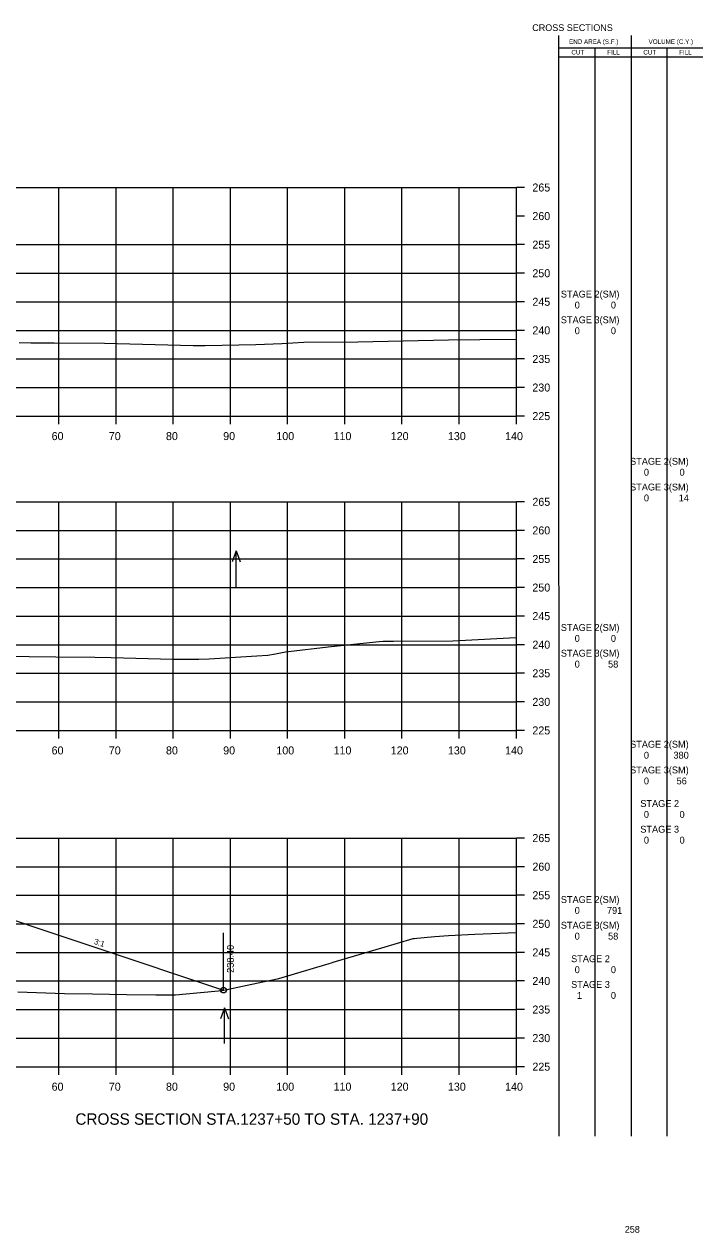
# Model space of a CAD drawing. Extents: x 1342547 to 1344156, y -1532351 to -1517216.
# Drawn here: x 1342756.8 to 1342875.5, y -1529164 to -1528952.5 of the extents above; entities that cross this region are included whole.
import ezdxf

# ---------------------------------------------------------------- set-up
doc = ezdxf.new("R2010")
doc.units = 0
for name, color, linetype in [('Level 2', 7, 'Continuous'), ('R_Axis', 7, 'Continuous'), ('R_Axis Annot', 7, 'Continuous'), ('R_Border Notes', 7, 'Continuous'), ('R_Draft', 7, 'Continuous'), ('R_Exist Surface', 7, 'Continuous'), ('R_Fin Surface', 7, 'Continuous'), ('R_Grid', 7, 'Continuous'), ('R_No Plot', 7, 'Continuous'), ('R_Water', 7, 'Continuous'), ('R_Xsect Elev', 7, 'Continuous'), ('R_Xsect Slope', 7, 'Continuous')]:
    doc.layers.add(name, color=color, linetype=linetype)

msp = doc.modelspace()

# ---------------------------------------------------------------- linework, layer by layer
at = {"layer": 'Level 2'}
for p, q in [((1342850.33, -1529147.08), (1342850.32, -1528954.48)), ((1342862.99, -1529147.08), (1342862.99, -1528954.48)), ((1342850.32, -1528956.64), (1342863.59, -1528956.64)), ((1342856.66, -1529147.08), (1342856.66, -1528956.64)), ((1342863.59, -1528956.64), (1342875.48, -1528956.64)), ((1342869.23, -1529147.08), (1342869.23, -1528956.64)), ((1342850.32, -1528958.2), (1342863.59, -1528958.2)), ((1342863.59, -1528958.2), (1342875.48, -1528958.2))]:
    msp.add_line(p, q, dxfattribs=at)
at = {"layer": 'R_Axis'}
for p, q in [((1342842.87, -1529021.08), (1342842.87, -1528981.08)), ((1342844.27, -1528981.08), (1342842.87, -1528981.08)), ((1342844.27, -1528986.08), (1342842.87, -1528986.08)), ((1342844.27, -1528991.08), (1342842.87, -1528991.08)), ((1342844.27, -1528996.08), (1342842.87, -1528996.08)), ((1342844.27, -1529001.08), (1342842.87, -1529001.08)), ((1342844.27, -1529006.08), (1342842.87, -1529006.08)), ((1342844.27, -1529011.08), (1342842.87, -1529011.08)), ((1342844.27, -1529016.08), (1342842.87, -1529016.08)), ((1342562.87, -1529021.08), (1342842.87, -1529021.08)), ((1342762.87, -1529022.48), (1342762.87, -1529021.08)), ((1342772.87, -1529022.48), (1342772.87, -1529021.08)), ((1342782.87, -1529022.48), (1342782.87, -1529021.08)), ((1342792.87, -1529022.48), (1342792.87, -1529021.08)), ((1342802.87, -1529022.48), (1342802.87, -1529021.08)), ((1342812.87, -1529022.48), (1342812.87, -1529021.08)), ((1342822.87, -1529022.48), (1342822.87, -1529021.08)), ((1342832.87, -1529022.48), (1342832.87, -1529021.08)), ((1342842.87, -1529022.48), (1342842.87, -1529021.08)), ((1342844.27, -1529021.08), (1342842.87, -1529021.08)), ((1342842.87, -1529076.08), (1342842.87, -1529036.08)), ((1342844.27, -1529036.08), (1342842.87, -1529036.08)), ((1342844.27, -1529041.08), (1342842.87, -1529041.08)), ((1342844.27, -1529046.08), (1342842.87, -1529046.08)), ((1342844.27, -1529051.08), (1342842.87, -1529051.08)), ((1342844.27, -1529056.08), (1342842.87, -1529056.08)), ((1342844.27, -1529061.08), (1342842.87, -1529061.08)), ((1342844.27, -1529066.08), (1342842.87, -1529066.08)), ((1342844.27, -1529071.08), (1342842.87, -1529071.08)), ((1342562.87, -1529076.08), (1342842.87, -1529076.08)), ((1342762.87, -1529077.48), (1342762.87, -1529076.08)), ((1342772.87, -1529077.48), (1342772.87, -1529076.08)), ((1342782.87, -1529077.48), (1342782.87, -1529076.08)), ((1342792.87, -1529077.48), (1342792.87, -1529076.08)), ((1342802.87, -1529077.48), (1342802.87, -1529076.08)), ((1342812.87, -1529077.48), (1342812.87, -1529076.08)), ((1342822.87, -1529077.48), (1342822.87, -1529076.08)), ((1342832.87, -1529077.48), (1342832.87, -1529076.08)), ((1342842.87, -1529077.48), (1342842.87, -1529076.08)), ((1342844.27, -1529076.08), (1342842.87, -1529076.08)), ((1342842.87, -1529134.92), (1342842.87, -1529094.92)), ((1342844.27, -1529094.92), (1342842.87, -1529094.92)), ((1342844.27, -1529099.92), (1342842.87, -1529099.92)), ((1342844.27, -1529104.92), (1342842.87, -1529104.92)), ((1342844.27, -1529109.92), (1342842.87, -1529109.92)), ((1342844.27, -1529114.92), (1342842.87, -1529114.92)), ((1342844.27, -1529119.92), (1342842.87, -1529119.92)), ((1342844.27, -1529124.92), (1342842.87, -1529124.92)), ((1342844.27, -1529129.92), (1342842.87, -1529129.92)), ((1342562.87, -1529134.92), (1342842.87, -1529134.92)), ((1342762.87, -1529136.32), (1342762.87, -1529134.92)), ((1342772.87, -1529136.32), (1342772.87, -1529134.92)), ((1342782.87, -1529136.32), (1342782.87, -1529134.92)), ((1342792.87, -1529136.32), (1342792.87, -1529134.92)), ((1342802.87, -1529136.32), (1342802.87, -1529134.92)), ((1342812.87, -1529136.32), (1342812.87, -1529134.92)), ((1342822.87, -1529136.32), (1342822.87, -1529134.92)), ((1342832.87, -1529136.32), (1342832.87, -1529134.92)), ((1342842.87, -1529136.32), (1342842.87, -1529134.92)), ((1342844.27, -1529134.92), (1342842.87, -1529134.92))]:
    msp.add_line(p, q, dxfattribs=at)
at = {"layer": 'R_Exist Surface'}
for points in [[(1342755.91, -1529008.21), (1342757.97, -1529008.26), (1342762.04, -1529008.28), (1342770.87, -1529008.29), (1342786.38, -1529008.71), (1342786.97, -1529008.72), (1342788.46, -1529008.7), (1342797.3, -1529008.58), (1342801.84, -1529008.36), (1342805.71, -1529008.15), (1342815.14, -1529008.06), (1342831.01, -1529007.72), (1342836.46, -1529007.68), (1342842.87, -1529007.61)], [(1342754.94, -1529063.11), (1342757.66, -1529063.17), (1342762.35, -1529063.2), (1342769.14, -1529063.28), (1342772, -1529063.34), (1342782.82, -1529063.64), (1342787.32, -1529063.62), (1342789.15, -1529063.58), (1342797.5, -1529063.04), (1342799.41, -1529062.89), (1342800.78, -1529062.65), (1342802.52, -1529062.34), (1342810.51, -1529061.38), (1342818.9, -1529060.51), (1342819.6, -1529060.47), (1342821.41, -1529060.48), (1342831.79, -1529060.42), (1342832.88, -1529060.37), (1342842.77, -1529059.81), (1342842.87, -1529059.8)], [(1342755.69, -1529121.81), (1342763.85, -1529122.13), (1342768.74, -1529122.18), (1342774.7, -1529122.3), (1342779.84, -1529122.34), (1342783.26, -1529122.33), (1342786.99, -1529122.02), (1342791.42, -1529121.56), (1342798.51, -1529120.06), (1342801.32, -1529119.46), (1342810.15, -1529116.85), (1342810.57, -1529116.72), (1342810.86, -1529116.63), (1342811.39, -1529116.43), (1342819.36, -1529114.13), (1342824.84, -1529112.51), (1342824.98, -1529112.48), (1342825.47, -1529112.41), (1342828.61, -1529112.12), (1342831.01, -1529111.98), (1342835.61, -1529111.75), (1342842.87, -1529111.43)]]:
    msp.add_lwpolyline(points, dxfattribs=at)
at = {"layer": 'R_Fin Surface'}
msp.add_lwpolyline([(1342649.15, -1529113.28), (1342653.18, -1529113.2), (1342659.86, -1529110.98), (1342659.87, -1529110.98), (1342671.37, -1529110.35), (1342673.37, -1529110.24), (1342702.87, -1529108.61), (1342732.37, -1529106.99), (1342734.37, -1529106.88), (1342745.87, -1529106.25), (1342745.88, -1529106.25), (1342791.66, -1529121.51)], dxfattribs=at)
at = {"layer": 'R_Grid'}
for p, q in [((1342562.87, -1528981.08), (1342842.87, -1528981.08)), ((1342762.87, -1529021.08), (1342762.87, -1528981.08)), ((1342772.87, -1529021.08), (1342772.87, -1528981.08)), ((1342782.87, -1529021.08), (1342782.87, -1528981.08)), ((1342792.87, -1529021.08), (1342792.87, -1528981.08)), ((1342802.87, -1529021.08), (1342802.87, -1528981.08)), ((1342812.87, -1529021.08), (1342812.87, -1528981.08)), ((1342822.87, -1529021.08), (1342822.87, -1528981.08)), ((1342832.87, -1529021.08), (1342832.87, -1528981.08)), ((1342842.87, -1529021.08), (1342842.87, -1528981.08)), ((1342562.87, -1528991.08), (1342842.87, -1528991.08)), ((1342562.87, -1528996.08), (1342842.87, -1528996.08)), ((1342562.87, -1529001.08), (1342842.87, -1529001.08)), ((1342562.87, -1529006.08), (1342842.87, -1529006.08)), ((1342562.87, -1529011.08), (1342842.87, -1529011.08)), ((1342562.87, -1529016.08), (1342842.87, -1529016.08)), ((1342562.87, -1529021.08), (1342842.87, -1529021.08)), ((1342562.87, -1529036.08), (1342842.87, -1529036.08)), ((1342762.87, -1529076.08), (1342762.87, -1529036.08)), ((1342772.87, -1529076.08), (1342772.87, -1529036.08)), ((1342782.87, -1529076.08), (1342782.87, -1529036.08)), ((1342792.87, -1529076.08), (1342792.87, -1529036.08)), ((1342802.87, -1529076.08), (1342802.87, -1529036.08)), ((1342812.87, -1529076.08), (1342812.87, -1529036.08)), ((1342822.87, -1529076.08), (1342822.87, -1529036.08)), ((1342832.87, -1529076.08), (1342832.87, -1529036.08)), ((1342842.87, -1529076.08), (1342842.87, -1529036.08)), ((1342562.87, -1529041.08), (1342842.87, -1529041.08)), ((1342562.87, -1529046.08), (1342842.87, -1529046.08)), ((1342562.87, -1529051.08), (1342842.87, -1529051.08)), ((1342562.87, -1529056.08), (1342842.87, -1529056.08)), ((1342562.87, -1529061.08), (1342842.87, -1529061.08)), ((1342562.87, -1529066.08), (1342842.87, -1529066.08)), ((1342562.87, -1529071.08), (1342842.87, -1529071.08)), ((1342562.87, -1529076.08), (1342842.87, -1529076.08)), ((1342562.87, -1529094.92), (1342842.87, -1529094.92)), ((1342762.87, -1529134.92), (1342762.87, -1529094.92)), ((1342772.87, -1529134.92), (1342772.87, -1529094.92)), ((1342782.87, -1529134.92), (1342782.87, -1529094.92)), ((1342792.87, -1529134.92), (1342792.87, -1529094.92)), ((1342802.87, -1529134.92), (1342802.87, -1529094.92)), ((1342812.87, -1529134.92), (1342812.87, -1529094.92)), ((1342822.87, -1529134.92), (1342822.87, -1529094.92)), ((1342832.87, -1529134.92), (1342832.87, -1529094.92)), ((1342842.87, -1529134.92), (1342842.87, -1529094.92)), ((1342562.87, -1529099.92), (1342842.87, -1529099.92)), ((1342562.87, -1529104.92), (1342842.87, -1529104.92)), ((1342562.87, -1529109.92), (1342842.87, -1529109.92)), ((1342562.87, -1529114.92), (1342842.87, -1529114.92)), ((1342562.87, -1529119.92), (1342842.87, -1529119.92)), ((1342562.87, -1529124.92), (1342842.87, -1529124.92)), ((1342562.87, -1529129.92), (1342842.87, -1529129.92)), ((1342562.87, -1529134.92), (1342842.87, -1529134.92))]:
    msp.add_line(p, q, dxfattribs=at)
at = {"layer": 'R_No Plot'}
msp.add_circle((1342791.66, -1529121.51), 0.5, dxfattribs=at)
at = {"layer": 'R_Water'}
for p, q in [((1342793.86, -1529044.66), (1342793.16, -1529046.59)), ((1342793.86, -1529050.95), (1342793.86, -1529044.66)), ((1342793.86, -1529044.66), (1342794.56, -1529046.59)), ((1342791.84, -1529124.6), (1342791.14, -1529126.52)), ((1342791.84, -1529130.88), (1342791.84, -1529124.6)), ((1342791.84, -1529124.6), (1342792.54, -1529126.52))]:
    msp.add_line(p, q, dxfattribs=at)
at = {"layer": 'R_Xsect Elev'}
msp.add_line((1342791.66, -1529121.51), (1342791.66, -1529111.51), dxfattribs=at)

# ---------------------------------------------------------------- texts
at = {"layer": 'Level 2'}
for s, height, p in [('END AREA (S.F.)', 0.7937, (1342852.08, -1528955.95)), ('CUT', 0.794, (1342852.5, -1528957.81)), ('FILL', 0.794, (1342858.76, -1528957.81)), ('CUT', 0.794, (1342865.07, -1528957.81)), ('VOLUME (C.Y.)', 0.7937, (1342865.99, -1528955.95)), ('FILL', 0.794, (1342871.33, -1528957.81)), (' STAGE 2(SM)  ', 1.2, (1342850.2, -1529000.33)), ('0', 1.2, (1342853.07, -1529002.25)), ('0', 1.2, (1342859.4, -1529002.25)), (' STAGE 3(SM)  ', 1.2, (1342850.2, -1529004.83)), ('0', 1.2, (1342853.07, -1529006.75)), ('0', 1.2, (1342859.4, -1529006.75)), (' STAGE 2(SM)  ', 1.2, (1342862.31, -1529029.59)), ('0', 1.2, (1342865.17, -1529031.5)), ('0', 1.2, (1342871.41, -1529031.5)), (' STAGE 3(SM)  ', 1.2, (1342862.31, -1529034.09)), ('0', 1.2, (1342865.17, -1529036)), ('14', 1.2, (1342871.27, -1529036)), (' STAGE 2(SM)  ', 1.2, (1342850.2, -1529058.67)), ('0', 1.2, (1342853.07, -1529060.58)), ('0', 1.2, (1342859.4, -1529060.58)), (' STAGE 3(SM)  ', 1.2, (1342850.2, -1529063.17)), ('0', 1.2, (1342853.07, -1529065.08)), ('58', 1.2, (1342858.91, -1529065.08)), (' STAGE 2(SM)  ', 1.2, (1342862.31, -1529079.1)), ('0', 1.2, (1342865.17, -1529081.02)), ('380', 1.2, (1342870.34, -1529081.02)), (' STAGE 3(SM)  ', 1.2, (1342862.31, -1529083.6)), ('0', 1.2, (1342865.17, -1529085.52)), ('56', 1.2, (1342870.89, -1529085.52)), (' STAGE 2 ', 1.2, (1342864.1, -1529089.47)), ('0', 1.2, (1342865.17, -1529091.38)), ('0', 1.2, (1342871.41, -1529091.38)), (' STAGE 3 ', 1.2, (1342864.1, -1529093.97)), ('0', 1.2, (1342865.17, -1529095.88)), ('0', 1.2, (1342871.41, -1529095.88)), (' STAGE 2(SM)  ', 1.2, (1342850.2, -1529106.27)), ('0', 1.2, (1342853.07, -1529108.18)), ('791', 1.2, (1342858.71, -1529108.18)), (' STAGE 3(SM)  ', 1.2, (1342850.2, -1529110.77)), ('0', 1.2, (1342853.07, -1529112.68)), ('58', 1.2, (1342858.91, -1529112.68)), (' STAGE 2 ', 1.2, (1342852, -1529116.63)), ('0', 1.2, (1342853.07, -1529118.55)), ('0', 1.2, (1342859.4, -1529118.55)), (' STAGE 3 ', 1.2, (1342852, -1529121.13)), ('1', 1.2, (1342853.46, -1529123.05)), ('0', 1.2, (1342859.4, -1529123.05))]:
    msp.add_text(s, height=height, dxfattribs=at).set_placement(p)
at = {"layer": 'R_Axis Annot'}
for s, p in [('265', (1342845.67, -1528981.78)), ('260', (1342845.67, -1528986.78)), ('255', (1342845.67, -1528991.78)), ('250', (1342845.67, -1528996.78)), ('245', (1342845.67, -1529001.78)), ('240', (1342845.67, -1529006.78)), ('235', (1342845.67, -1529011.78)), ('230', (1342845.67, -1529016.78)), ('225', (1342845.67, -1529021.78)), ('60', (1342761.6, -1529025.28)), ('70', (1342771.6, -1529025.28)), ('80', (1342781.6, -1529025.28)), ('90', (1342791.6, -1529025.28)), ('100', (1342800.9, -1529025.28)), ('110', (1342810.9, -1529025.28)), ('120', (1342820.9, -1529025.28)), ('130', (1342830.9, -1529025.28)), ('140', (1342840.9, -1529025.28)), ('265', (1342845.67, -1529036.78)), ('260', (1342845.67, -1529041.78)), ('255', (1342845.67, -1529046.78)), ('250', (1342845.67, -1529051.78)), ('245', (1342845.67, -1529056.78)), ('240', (1342845.67, -1529061.78)), ('235', (1342845.67, -1529066.78)), ('230', (1342845.67, -1529071.78)), ('225', (1342845.67, -1529076.78)), ('60', (1342761.6, -1529080.28)), ('70', (1342771.6, -1529080.28)), ('80', (1342781.6, -1529080.28)), ('90', (1342791.6, -1529080.28)), ('100', (1342800.9, -1529080.28)), ('110', (1342810.9, -1529080.28)), ('120', (1342820.9, -1529080.28)), ('130', (1342830.9, -1529080.28)), ('140', (1342840.9, -1529080.28)), ('265', (1342845.67, -1529095.62)), ('260', (1342845.67, -1529100.62)), ('255', (1342845.67, -1529105.62)), ('250', (1342845.67, -1529110.62)), ('245', (1342845.67, -1529115.62)), ('240', (1342845.67, -1529120.62)), ('235', (1342845.67, -1529125.62)), ('230', (1342845.67, -1529130.62)), ('225', (1342845.67, -1529135.62)), ('60', (1342761.6, -1529139.12)), ('70', (1342771.6, -1529139.12)), ('80', (1342781.6, -1529139.12)), ('90', (1342791.6, -1529139.12)), ('100', (1342800.9, -1529139.12)), ('110', (1342810.9, -1529139.12)), ('120', (1342820.9, -1529139.12)), ('130', (1342830.9, -1529139.12)), ('140', (1342840.9, -1529139.12))]:
    msp.add_text(s, height=1.4, dxfattribs=at).set_placement(p)
at = {"layer": 'R_Border Notes'}
for s, height, p in [('CROSS SECTIONS', 1.1775, (1342845.65, -1528953.7)), ('258', 1.178, (1342861.83, -1529163.97))]:
    msp.add_text(s, height=height, dxfattribs=at).set_placement(p)
at = {"layer": 'R_Draft'}
msp.add_text('CROSS SECTION STA.1237+50 TO STA. 1237+90', height=2, dxfattribs=at).set_placement((1342765.76, -1529145.08))
at = {"layer": 'R_Xsect Elev'}
msp.add_text('238.40', height=1.2, rotation=90, dxfattribs=at).set_placement((1342793.46, -1529118.51))
at = {"layer": 'R_Xsect Slope'}
msp.add_text('3:1', height=1, rotation=341.5651, dxfattribs=at).set_placement((1342768.93, -1529113.41))

doc.saveas('drawing.dxf')
